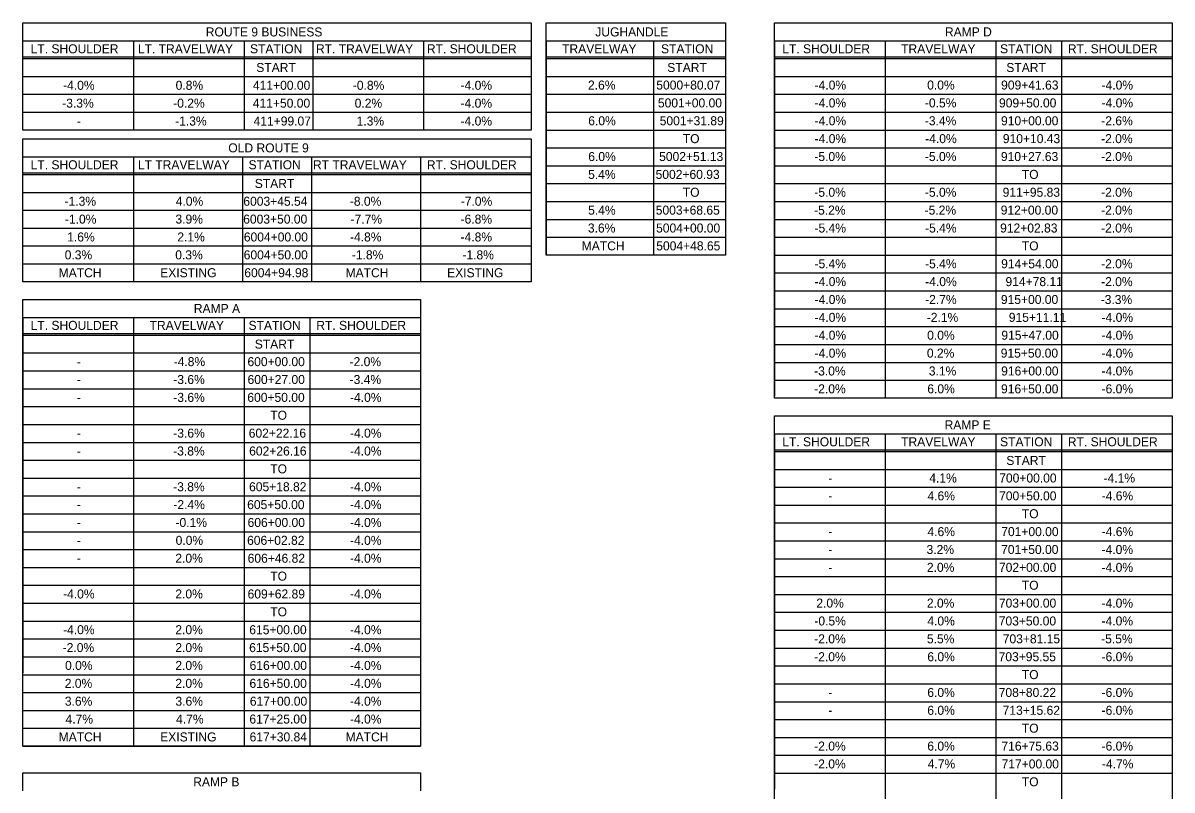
# Model space of a CAD drawing. Extents: x -15318841 to 1762012, y 465773 to 3693661.
# Drawn here: x -15310618.3 to -15310236.2, y 3691187.3 to 3691442.4 of the extents above; entities that cross this region are included whole.
import ezdxf

# ---------------------------------------------------------------- set-up
doc = ezdxf.new("R2010")
doc.units = 0
doc.layers.add('BORDER', color=7, linetype='Continuous')
doc.layers.add('DIMENSIONS', color=7, linetype='Continuous')

msp = doc.modelspace()

# ---------------------------------------------------------------- linework, layer by layer
at = {"layer": 'BORDER'}
for p, q in [((-15310581.57, 3691436.42), (-15310581.57, 3691406.77)), ((-15310544.8, 3691436.42), (-15310544.8, 3691406.77)), ((-15310521.92, 3691436.42), (-15310521.92, 3691406.77)), ((-15310485.16, 3691436.42), (-15310485.16, 3691406.77)), ((-15310485.16, 3691436.42), (-15310485.16, 3691406.77)), ((-15310444.39, 3691436.42), (-15310444.39, 3691365.17)), ((-15310408.62, 3691436.42), (-15310408.62, 3691365.17)), ((-15310384.75, 3691436.42), (-15310384.75, 3691365.17)), ((-15310368.41, 3691436.42), (-15310368.41, 3691318.22)), ((-15310331.64, 3691436.42), (-15310331.64, 3691317.63)), ((-15310294.87, 3691436.42), (-15310294.87, 3691317.63)), ((-15310273, 3691436.42), (-15310273, 3691317.63)), ((-15310618.33, 3691431.14), (-15310449.39, 3691431.14)), ((-15310618.33, 3691430.54), (-15310449.39, 3691430.54)), ((-15310444.39, 3691431.14), (-15310384.75, 3691431.14)), ((-15310444.39, 3691430.54), (-15310384.75, 3691430.54)), ((-15310368.41, 3691431.14), (-15310236.23, 3691431.14)), ((-15310368.41, 3691430.54), (-15310236.23, 3691430.54)), ((-15310618.33, 3691424.6), (-15310449.39, 3691424.6)), ((-15310618.33, 3691424.6), (-15310449.39, 3691424.6)), ((-15310618.33, 3691424.6), (-15310449.39, 3691424.6)), ((-15310444.39, 3691424.6), (-15310384.75, 3691424.6)), ((-15310444.39, 3691424.6), (-15310384.75, 3691424.6)), ((-15310444.39, 3691424.6), (-15310384.75, 3691424.6)), ((-15310368.41, 3691424.6), (-15310236.23, 3691424.6)), ((-15310368.41, 3691424.6), (-15310236.23, 3691424.6)), ((-15310368.41, 3691424.6), (-15310236.23, 3691424.6)), ((-15310618.33, 3691418.66), (-15310449.39, 3691418.66)), ((-15310444.39, 3691418.66), (-15310384.75, 3691418.66)), ((-15310368.41, 3691418.66), (-15310236.23, 3691418.66)), ((-15310618.33, 3691412.71), (-15310449.39, 3691412.71)), ((-15310444.39, 3691412.71), (-15310384.75, 3691412.71)), ((-15310368.41, 3691412.71), (-15310236.23, 3691412.71)), ((-15310444.39, 3691406.77), (-15310384.75, 3691406.77)), ((-15310368.41, 3691406.77), (-15310236.23, 3691406.77)), ((-15310444.39, 3691400.83), (-15310384.75, 3691400.83)), ((-15310368.41, 3691400.83), (-15310236.23, 3691400.83)), ((-15310581.57, 3691397.86), (-15310581.57, 3691356.32)), ((-15310545.3, 3691397.86), (-15310545.3, 3691356.32)), ((-15310522.42, 3691397.86), (-15310522.42, 3691356.32)), ((-15310486.16, 3691397.86), (-15310486.16, 3691356.32)), ((-15310618.33, 3691392.57), (-15310449.39, 3691392.57)), ((-15310618.33, 3691391.98), (-15310449.39, 3691391.98)), ((-15310444.39, 3691394.88), (-15310384.75, 3691394.88)), ((-15310368.41, 3691394.88), (-15310236.23, 3691394.88)), ((-15310444.39, 3691388.94), (-15310384.75, 3691388.94)), ((-15310368.41, 3691388.94), (-15310236.23, 3691388.94)), ((-15310618.33, 3691386.04), (-15310449.39, 3691386.04)), ((-15310618.33, 3691386.04), (-15310449.39, 3691386.04)), ((-15310618.33, 3691386.04), (-15310449.39, 3691386.04)), ((-15310618.33, 3691380.09), (-15310449.39, 3691380.09)), ((-15310444.39, 3691383), (-15310384.75, 3691383)), ((-15310368.41, 3691383), (-15310236.23, 3691383)), ((-15310444.39, 3691377.06), (-15310384.75, 3691377.06)), ((-15310368.41, 3691377.06), (-15310236.23, 3691377.06)), ((-15310618.33, 3691374.15), (-15310449.39, 3691374.15)), ((-15310444.39, 3691371.11), (-15310384.75, 3691371.11)), ((-15310368.41, 3691371.11), (-15310236.23, 3691371.11)), ((-15310618.33, 3691368.21), (-15310449.39, 3691368.21)), ((-15310368.41, 3691365.17), (-15310236.23, 3691365.17)), ((-15310618.33, 3691362.26), (-15310449.39, 3691362.26)), ((-15310368.41, 3691359.23), (-15310236.23, 3691359.23)), ((-15310368.41, 3691353.29), (-15310236.23, 3691353.29)), ((-15310368.41, 3691347.34), (-15310236.23, 3691347.34)), ((-15310618.33, 3691344.44), (-15310618.33, 3691226.24)), ((-15310581.57, 3691344.44), (-15310581.57, 3691219.71)), ((-15310544.8, 3691344.44), (-15310544.8, 3691219.71)), ((-15310522.92, 3691344.44), (-15310522.92, 3691219.71)), ((-15310486.16, 3691344.44), (-15310486.16, 3691219.71)), ((-15310618.33, 3691339.15), (-15310486.16, 3691339.15)), ((-15310618.33, 3691338.56), (-15310486.16, 3691338.56)), ((-15310368.41, 3691341.4), (-15310236.23, 3691341.4)), ((-15310368.41, 3691335.46), (-15310236.23, 3691335.46)), ((-15310618.33, 3691332.62), (-15310486.16, 3691332.62)), ((-15310618.33, 3691332.62), (-15310486.16, 3691332.62)), ((-15310618.33, 3691332.62), (-15310486.16, 3691332.62)), ((-15310618.33, 3691326.67), (-15310486.16, 3691326.67)), ((-15310368.41, 3691329.51), (-15310236.23, 3691329.51)), ((-15310368.41, 3691323.57), (-15310236.23, 3691323.57)), ((-15310618.33, 3691320.73), (-15310486.16, 3691320.73)), ((-15310618.33, 3691314.79), (-15310486.16, 3691314.79)), ((-15310618.33, 3691308.85), (-15310486.16, 3691308.85)), ((-15310368.41, 3691305.74), (-15310368.41, 3691187.54)), ((-15310331.64, 3691305.74), (-15310331.64, 3691139.41)), ((-15310294.87, 3691305.74), (-15310294.87, 3691139.41)), ((-15310273, 3691305.74), (-15310273, 3691139.41)), ((-15310618.33, 3691302.9), (-15310486.16, 3691302.9)), ((-15310368.41, 3691300.46), (-15310236.23, 3691300.46)), ((-15310368.41, 3691299.87), (-15310236.23, 3691299.87)), ((-15310618.33, 3691296.96), (-15310486.16, 3691296.96)), ((-15310368.41, 3691293.92), (-15310236.23, 3691293.92)), ((-15310368.41, 3691293.92), (-15310236.23, 3691293.92)), ((-15310368.41, 3691293.92), (-15310236.23, 3691293.92)), ((-15310618.33, 3691291.02), (-15310486.16, 3691291.02)), ((-15310618.33, 3691285.08), (-15310486.16, 3691285.08)), ((-15310368.41, 3691287.98), (-15310236.23, 3691287.98)), ((-15310368.41, 3691282.04), (-15310236.23, 3691282.04)), ((-15310618.33, 3691279.13), (-15310486.16, 3691279.13)), ((-15310618.33, 3691273.19), (-15310486.16, 3691273.19)), ((-15310368.41, 3691276.1), (-15310236.23, 3691276.1)), ((-15310368.41, 3691270.15), (-15310236.23, 3691270.15)), ((-15310618.33, 3691267.25), (-15310486.16, 3691267.25)), ((-15310368.41, 3691264.21), (-15310236.23, 3691264.21)), ((-15310618.33, 3691261.3), (-15310486.16, 3691261.3)), ((-15310368.41, 3691258.27), (-15310236.23, 3691258.27)), ((-15310618.33, 3691255.36), (-15310486.16, 3691255.36)), ((-15310368.41, 3691252.32), (-15310236.23, 3691252.32)), ((-15310618.33, 3691249.42), (-15310486.16, 3691249.42)), ((-15310368.41, 3691246.38), (-15310236.23, 3691246.38)), ((-15310618.33, 3691243.48), (-15310486.16, 3691243.48)), ((-15310368.41, 3691240.44), (-15310236.23, 3691240.44)), ((-15310618.33, 3691237.53), (-15310486.16, 3691237.53)), ((-15310618.33, 3691231.59), (-15310486.16, 3691231.59)), ((-15310368.41, 3691234.5), (-15310236.23, 3691234.5)), ((-15310368.41, 3691228.55), (-15310236.23, 3691228.55)), ((-15310618.33, 3691225.65), (-15310486.16, 3691225.65)), ((-15310618.33, 3691219.71), (-15310486.16, 3691219.71)), ((-15310581.57, 3691219.71), (-15310581.57, 3691201.88)), ((-15310544.8, 3691219.71), (-15310544.8, 3691201.88)), ((-15310522.92, 3691219.71), (-15310522.92, 3691201.88)), ((-15310368.41, 3691222.61), (-15310236.23, 3691222.61)), ((-15310368.41, 3691216.67), (-15310236.23, 3691216.67)), ((-15310618.33, 3691213.76), (-15310486.16, 3691213.76)), ((-15310368.41, 3691210.73), (-15310236.23, 3691210.73)), ((-15310618.33, 3691207.82), (-15310486.16, 3691207.82)), ((-15310368.41, 3691204.78), (-15310236.23, 3691204.78)), ((-15310618.33, 3691201.88), (-15310486.16, 3691201.88)), ((-15310368.41, 3691198.84), (-15310236.23, 3691198.84)), ((-15310368.41, 3691192.9), (-15310236.23, 3691192.9))]:
    msp.add_line(p, q, dxfattribs=at)
for points in [[(-15310618.33, 3691436.42), (-15310618.33, 3691442.36), (-15310449.39, 3691442.36), (-15310449.39, 3691436.42)], [(-15310444.39, 3691436.42), (-15310444.39, 3691442.36), (-15310384.75, 3691442.36), (-15310384.75, 3691436.42)], [(-15310368.41, 3691436.42), (-15310368.41, 3691442.36), (-15310236.23, 3691442.36), (-15310236.23, 3691436.42)], [(-15310618.33, 3691397.86), (-15310618.33, 3691403.8), (-15310449.39, 3691403.8), (-15310449.39, 3691397.86)], [(-15310618.33, 3691344.44), (-15310618.33, 3691350.38), (-15310486.16, 3691350.38), (-15310486.16, 3691344.44)], [(-15310368.41, 3691305.74), (-15310368.41, 3691311.69), (-15310236.23, 3691311.69), (-15310236.23, 3691305.74)], [(-15310618.33, 3691187.04), (-15310618.33, 3691192.98), (-15310486.16, 3691192.98), (-15310486.16, 3691187.04)]]:
    msp.add_lwpolyline(points, dxfattribs=at)
for points in [[(-15310618.33, 3691436.42), (-15310449.39, 3691436.42), (-15310449.39, 3691406.77), (-15310618.33, 3691406.77)], [(-15310444.39, 3691436.42), (-15310384.75, 3691436.42), (-15310384.75, 3691365.17), (-15310444.39, 3691365.17)], [(-15310368.41, 3691436.42), (-15310236.23, 3691436.42), (-15310236.23, 3691317.63), (-15310368.41, 3691317.63)], [(-15310618.33, 3691397.86), (-15310449.39, 3691397.86), (-15310449.39, 3691356.32), (-15310618.33, 3691356.32)], [(-15310618.33, 3691344.44), (-15310486.16, 3691344.44), (-15310486.16, 3691201.88), (-15310618.33, 3691201.88)], [(-15310368.41, 3691305.74), (-15310236.23, 3691305.74), (-15310236.23, 3691139.41), (-15310368.41, 3691139.41)]]:
    msp.add_lwpolyline(points, close=True, dxfattribs=at)

# ---------------------------------------------------------------- texts
at = {"layer": 'DIMENSIONS'}
for s, p in [('ROUTE 9 BUSINESS', (-15310557.55, 3691437.89)), ('JUGHANDLE', (-15310428.02, 3691437.89)), ('RAMP D', (-15310311.75, 3691437.89)), ('LT. SHOULDER', (-15310615.78, 3691432.28)), ('LT. TRAVELWAY', (-15310580.12, 3691432.28)), ('STATION', (-15310542.83, 3691432.28)), ('RT. TRAVELWAY', (-15310520.9, 3691432.28)), ('RT. SHOULDER', (-15310484.03, 3691432.28)), ('TRAVELWAY', (-15310439.06, 3691432.28)), ('STATION', (-15310406.16, 3691432.28)), ('LT. SHOULDER', (-15310365.85, 3691432.28)), ('TRAVELWAY', (-15310326.32, 3691432.28)), ('STATION', (-15310293.41, 3691432.28)), ('RT. SHOULDER', (-15310270.87, 3691432.28)), ('START', (-15310540.76, 3691426.05)), ('START', (-15310404.08, 3691426.05)), ('START', (-15310291.33, 3691426.05)), ('-4.0%', (-15310605, 3691420.14)), ('0.8%', (-15310567.57, 3691420.14)), ('411+00.00', (-15310541.86, 3691420.14)), ('-0.8%', (-15310508.64, 3691420.14)), ('-4.0%', (-15310472.82, 3691420.14)), ('2.6%', (-15310430.44, 3691420.22)), ('5000+80.07', (-15310407.73, 3691420.22)), ('-4.0%', (-15310355.08, 3691420.22)), ('0.0%', (-15310317.65, 3691420.22)), ('909+41.63', (-15310293.06, 3691420.22)), ('-4.0%', (-15310259.66, 3691420.22)), ('-3.3%', (-15310605.29, 3691414.2)), ('-0.2%', (-15310568.38, 3691414.2)), ('411+50.00', (-15310541.91, 3691414.2)), ('0.2%', (-15310508.03, 3691414.2)), ('-4.0%', (-15310472.82, 3691414.2)), ('5001+00.00', (-15310407.19, 3691414.28)), ('-4.0%', (-15310355.08, 3691414.28)), ('-0.5%', (-15310318.4, 3691414.28)), ('909+50.00', (-15310293.76, 3691414.28)), ('-4.0%', (-15310259.66, 3691414.28)), ('-1.3%', (-15310567.74, 3691408.26)), ('411+99.07', (-15310541.65, 3691408.26)), ('1.3%', (-15310507.39, 3691408.26)), ('-4.0%', (-15310472.82, 3691408.26)), ('6.0%', (-15310430.35, 3691408.34)), ('5001+31.89', (-15310406.6, 3691408.34)), ('-4.0%', (-15310355.08, 3691408.34)), ('-3.4%', (-15310318.43, 3691408.34)), ('910+00.00', (-15310293.09, 3691408.34)), ('-2.6%', (-15310259.76, 3691408.34)), ('-', (-15310600.46, 3691408.26)), ('TO', (-15310398.92, 3691402.4)), ('-4.0%', (-15310355.08, 3691402.4)), ('-4.0%', (-15310318.31, 3691402.4)), ('910+10.43', (-15310292.49, 3691402.4)), ('-2.0%', (-15310259.81, 3691402.4)), ('OLD ROUTE 9', (-15310550.05, 3691399.33)), ('6.0%', (-15310430.35, 3691396.45)), ('5002+51.13', (-15310406.78, 3691396.45)), ('-5.0%', (-15310355.17, 3691396.45)), ('-5.0%', (-15310318.4, 3691396.45)), ('910+27.63', (-15310293.13, 3691396.45)), ('-2.0%', (-15310259.81, 3691396.45)), ('LT. SHOULDER', (-15310615.78, 3691393.71)), ('LT TRAVELWAY', (-15310580.12, 3691393.71)), ('STATION', (-15310543.33, 3691393.71)), ('RT TRAVELWAY', (-15310521.9, 3691393.71)), ('RT. SHOULDER', (-15310484.03, 3691393.71)), ('5.4%', (-15310430.4, 3691390.51)), ('5002+60.93', (-15310407.96, 3691390.51)), ('TO', (-15310286.17, 3691390.51)), ('START', (-15310541.26, 3691387.49)), ('TO', (-15310398.92, 3691384.57)), ('-5.0%', (-15310355.17, 3691384.57)), ('-5.0%', (-15310318.4, 3691384.57)), ('911+95.83', (-15310292.54, 3691384.57)), ('-2.0%', (-15310259.81, 3691384.57)), ('-1.3%', (-15310604.51, 3691381.58)), ('4.0%', (-15310567.53, 3691381.58)), ('6003+45.54', (-15310545.05, 3691381.58)), ('-8.0%', (-15310509.64, 3691381.58)), ('-7.0%', (-15310472.75, 3691381.58)), ('5.4%', (-15310430.4, 3691378.63)), ('5003+68.65', (-15310407.91, 3691378.63)), ('-5.2%', (-15310355.26, 3691378.63)), ('-5.2%', (-15310318.5, 3691378.63)), ('912+00.00', (-15310293.19, 3691378.63)), ('-2.0%', (-15310259.81, 3691378.63)), ('-1.0%', (-15310604.39, 3691375.64)), ('3.9%', (-15310567.64, 3691375.64)), ('6003+50.00', (-15310545.1, 3691375.64)), ('-7.7%', (-15310509.4, 3691375.64)), ('-6.8%', (-15310472.82, 3691375.64)), ('1.6%', (-15310603.63, 3691369.7)), ('2.1%', (-15310567.01, 3691369.7)), ('6004+00.00', (-15310544.89, 3691369.7)), ('-4.8%', (-15310509.59, 3691369.7)), ('-4.8%', (-15310472.82, 3691369.7)), ('3.6%', (-15310430.47, 3691372.68)), ('5004+00.00', (-15310407.8, 3691372.68)), ('-5.4%', (-15310355.12, 3691372.68)), ('-5.4%', (-15310318.35, 3691372.68)), ('912+02.83', (-15310293.39, 3691372.68)), ('-2.0%', (-15310259.81, 3691372.68)), ('MATCH', (-15310432.53, 3691366.74)), ('5004+48.65', (-15310407.74, 3691366.74)), ('TO', (-15310286.17, 3691366.74)), ('0.3%', (-15310604.46, 3691363.75)), ('0.3%', (-15310567.69, 3691363.75)), ('6004+50.00', (-15310544.93, 3691363.75)), ('-1.8%', (-15310508.98, 3691363.75)), ('-1.8%', (-15310472.21, 3691363.75)), ('MATCH', (-15310606.47, 3691357.81)), ('EXISTING', (-15310572.71, 3691357.81)), ('6004+94.98', (-15310544.73, 3691357.81)), ('MATCH', (-15310511.06, 3691357.81)), ('EXISTING', (-15310477.3, 3691357.81)), ('-5.4%', (-15310355.12, 3691360.8)), ('-5.4%', (-15310318.35, 3691360.8)), ('914+54.00', (-15310293.05, 3691360.8)), ('-2.0%', (-15310259.81, 3691360.8)), ('-4.0%', (-15310355.08, 3691354.85)), ('-4.0%', (-15310318.31, 3691354.85)), ('914+78.11', (-15310291.61, 3691354.85)), ('-2.0%', (-15310259.81, 3691354.85)), ('-4.0%', (-15310355.08, 3691348.91)), ('-2.7%', (-15310318.33, 3691348.91)), ('915+00.00', (-15310293.14, 3691348.91)), ('-3.3%', (-15310259.95, 3691348.91)), ('RAMP A', (-15310561.52, 3691345.91)), ('-4.0%', (-15310355.08, 3691342.97)), ('-2.1%', (-15310317.79, 3691342.97)), ('915+11.11', (-15310290.5, 3691342.97)), ('-4.0%', (-15310259.66, 3691342.97)), ('LT. SHOULDER', (-15310615.78, 3691340.3)), ('TRAVELWAY', (-15310576.24, 3691340.3)), ('STATION', (-15310543.33, 3691340.3)), ('RT. SHOULDER', (-15310520.8, 3691340.3)), ('-4.0%', (-15310355.08, 3691337.03)), ('0.0%', (-15310317.65, 3691337.03)), ('915+47.00', (-15310292.98, 3691337.03)), ('-4.0%', (-15310259.66, 3691337.03)), ('START', (-15310541.26, 3691334.07)), ('-4.0%', (-15310355.08, 3691331.08)), ('0.2%', (-15310317.74, 3691331.08)), ('915+50.00', (-15310293.19, 3691331.08)), ('-4.0%', (-15310259.66, 3691331.08)), ('-4.8%', (-15310568.23, 3691328.24)), ('600+00.00', (-15310543.68, 3691328.24)), ('-2.0%', (-15310509.73, 3691328.24)), ('-', (-15310600.46, 3691328.24)), ('-3.0%', (-15310355.24, 3691325.14)), ('3.1%', (-15310317.1, 3691325.14)), ('916+00.00', (-15310293.05, 3691325.14)), ('-4.0%', (-15310259.66, 3691325.14)), ('-', (-15310600.46, 3691322.3)), ('-3.6%', (-15310568.35, 3691322.3)), ('600+27.00', (-15310543.66, 3691322.3)), ('-3.4%', (-15310509.71, 3691322.3)), ('-3.6%', (-15310568.35, 3691316.36)), ('600+50.00', (-15310543.73, 3691316.36)), ('-4.0%', (-15310509.59, 3691316.36)), ('-2.0%', (-15310355.22, 3691319.2)), ('6.0%', (-15310317.6, 3691319.2)), ('916+50.00', (-15310293.09, 3691319.2)), ('-6.0%', (-15310259.66, 3691319.2)), ('-', (-15310600.46, 3691316.36)), ('TO', (-15310536.1, 3691310.42)), ('-3.6%', (-15310568.35, 3691304.47)), ('602+22.16', (-15310543.26, 3691304.47)), ('-4.0%', (-15310509.59, 3691304.47)), ('RAMP E', (-15310311.86, 3691307.22)), ('-', (-15310600.46, 3691304.47)), ('LT. SHOULDER', (-15310365.85, 3691301.6)), ('TRAVELWAY', (-15310326.32, 3691301.6)), ('STATION', (-15310293.41, 3691301.6)), ('RT. SHOULDER', (-15310270.87, 3691301.6)), ('-', (-15310600.46, 3691298.53)), ('-3.8%', (-15310568.4, 3691298.53)), ('602+26.16', (-15310543.12, 3691298.53)), ('-4.0%', (-15310509.59, 3691298.53)), ('START', (-15310291.33, 3691295.38)), ('TO', (-15310536.1, 3691292.59)), ('4.1%', (-15310316.94, 3691289.55)), ('700+00.00', (-15310293.69, 3691289.55)), ('-4.1%', (-15310259, 3691289.55)), ('-3.8%', (-15310568.4, 3691286.64)), ('605+18.82', (-15310543.15, 3691286.64)), ('-4.0%', (-15310509.59, 3691286.64)), ('-', (-15310350.53, 3691289.55)), ('-', (-15310600.46, 3691286.64)), ('-', (-15310350.53, 3691283.61)), ('4.6%', (-15310317.55, 3691283.61)), ('700+50.00', (-15310293.73, 3691283.61)), ('-4.6%', (-15310259.62, 3691283.61)), ('-', (-15310600.46, 3691280.7)), ('-2.4%', (-15310568.33, 3691280.7)), ('605+50.00', (-15310543.78, 3691280.7)), ('-4.0%', (-15310509.59, 3691280.7)), ('TO', (-15310286.17, 3691277.67)), ('-0.1%', (-15310567.62, 3691274.76)), ('606+00.00', (-15310543.64, 3691274.76)), ('-4.0%', (-15310509.59, 3691274.76)), ('-', (-15310600.46, 3691274.76)), ('-', (-15310350.53, 3691271.72)), ('4.6%', (-15310317.55, 3691271.72)), ('701+00.00', (-15310293.02, 3691271.72)), ('-4.6%', (-15310259.62, 3691271.72)), ('-', (-15310600.46, 3691268.82)), ('0.0%', (-15310567.57, 3691268.82)), ('606+02.82', (-15310543.81, 3691268.82)), ('-4.0%', (-15310509.59, 3691268.82)), ('2.0%', (-15310567.67, 3691262.87)), ('606+46.82', (-15310543.62, 3691262.87)), ('-4.0%', (-15310509.59, 3691262.87)), ('-', (-15310350.53, 3691265.78)), ('3.2%', (-15310317.86, 3691265.78)), ('701+50.00', (-15310293.07, 3691265.78)), ('-4.0%', (-15310259.66, 3691265.78)), ('-', (-15310600.46, 3691262.87)), ('2.0%', (-15310317.74, 3691259.84)), ('702+00.00', (-15310293.78, 3691259.84)), ('-4.0%', (-15310259.66, 3691259.84)), ('TO', (-15310536.1, 3691256.93)), ('-', (-15310350.53, 3691259.84)), ('-4.0%', (-15310605, 3691250.99)), ('2.0%', (-15310567.67, 3691250.99)), ('609+62.89', (-15310543.64, 3691250.99)), ('-4.0%', (-15310509.59, 3691250.99)), ('TO', (-15310286.17, 3691253.89)), ('2.0%', (-15310354.51, 3691247.95)), ('2.0%', (-15310317.74, 3691247.95)), ('703+00.00', (-15310293.8, 3691247.95)), ('-4.0%', (-15310259.66, 3691247.95)), ('TO', (-15310536.1, 3691245.05)), ('-0.5%', (-15310355.17, 3691242.01)), ('4.0%', (-15310317.6, 3691242.01)), ('703+50.00', (-15310293.85, 3691242.01)), ('-4.0%', (-15310259.66, 3691242.01)), ('-4.0%', (-15310605, 3691239.1)), ('2.0%', (-15310567.67, 3691239.1)), ('615+00.00', (-15310543.07, 3691239.1)), ('-4.0%', (-15310509.59, 3691239.1)), ('-2.0%', (-15310355.22, 3691236.07)), ('5.5%', (-15310317.74, 3691236.07)), ('703+81.15', (-15310292.52, 3691236.07)), ('-5.5%', (-15310259.81, 3691236.07)), ('-2.0%', (-15310605.14, 3691233.16)), ('2.0%', (-15310567.67, 3691233.16)), ('615+50.00', (-15310543.12, 3691233.16)), ('-4.0%', (-15310509.59, 3691233.16)), ('-2.0%', (-15310355.22, 3691230.12)), ('6.0%', (-15310317.6, 3691230.12)), ('703+95.55', (-15310293.89, 3691230.12)), ('-6.0%', (-15310259.66, 3691230.12)), ('0.0%', (-15310604.34, 3691227.22)), ('2.0%', (-15310567.67, 3691227.22)), ('616+00.00', (-15310542.97, 3691227.22)), ('-4.0%', (-15310509.59, 3691227.22)), ('TO', (-15310286.17, 3691224.18)), ('2.0%', (-15310604.44, 3691221.27)), ('2.0%', (-15310567.67, 3691221.27)), ('616+50.00', (-15310543.02, 3691221.27)), ('-4.0%', (-15310509.59, 3691221.27)), ('-', (-15310350.53, 3691218.24)), ('6.0%', (-15310317.6, 3691218.24)), ('708+80.22', (-15310293.86, 3691218.24)), ('-6.0%', (-15310259.66, 3691218.24)), ('3.6%', (-15310604.41, 3691215.33)), ('3.6%', (-15310567.64, 3691215.33)), ('617+00.00', (-15310542.9, 3691215.33)), ('-4.0%', (-15310509.59, 3691215.33)), ('4.7%', (-15310604.18, 3691209.39)), ('4.7%', (-15310567.41, 3691209.39)), ('617+25.00', (-15310543.05, 3691209.39)), ('-4.0%', (-15310509.59, 3691209.39)), ('-', (-15310350.53, 3691212.3)), ('6.0%', (-15310317.6, 3691212.3)), ('713+15.62', (-15310292.56, 3691212.3)), ('-6.0%', (-15310259.66, 3691212.3)), ('TO', (-15310286.17, 3691206.35)), ('MATCH', (-15310606.47, 3691203.45)), ('EXISTING', (-15310572.71, 3691203.45)), ('617+30.84', (-15310542.97, 3691203.45)), ('MATCH', (-15310511.06, 3691203.45)), ('-2.0%', (-15310355.22, 3691200.41)), ('6.0%', (-15310317.6, 3691200.41)), ('716+75.63', (-15310292.96, 3691200.41)), ('-6.0%', (-15310259.66, 3691200.41)), ('-2.0%', (-15310355.22, 3691194.47)), ('4.7%', (-15310317.48, 3691194.47)), ('717+00.00', (-15310292.91, 3691194.47)), ('-4.7%', (-15310259.55, 3691194.47)), ('RAMP B', (-15310561.72, 3691188.51)), ('TO', (-15310286.17, 3691188.52))]:
    msp.add_text(s, height=3, dxfattribs=at).set_placement(p)

doc.saveas('drawing.dxf')
